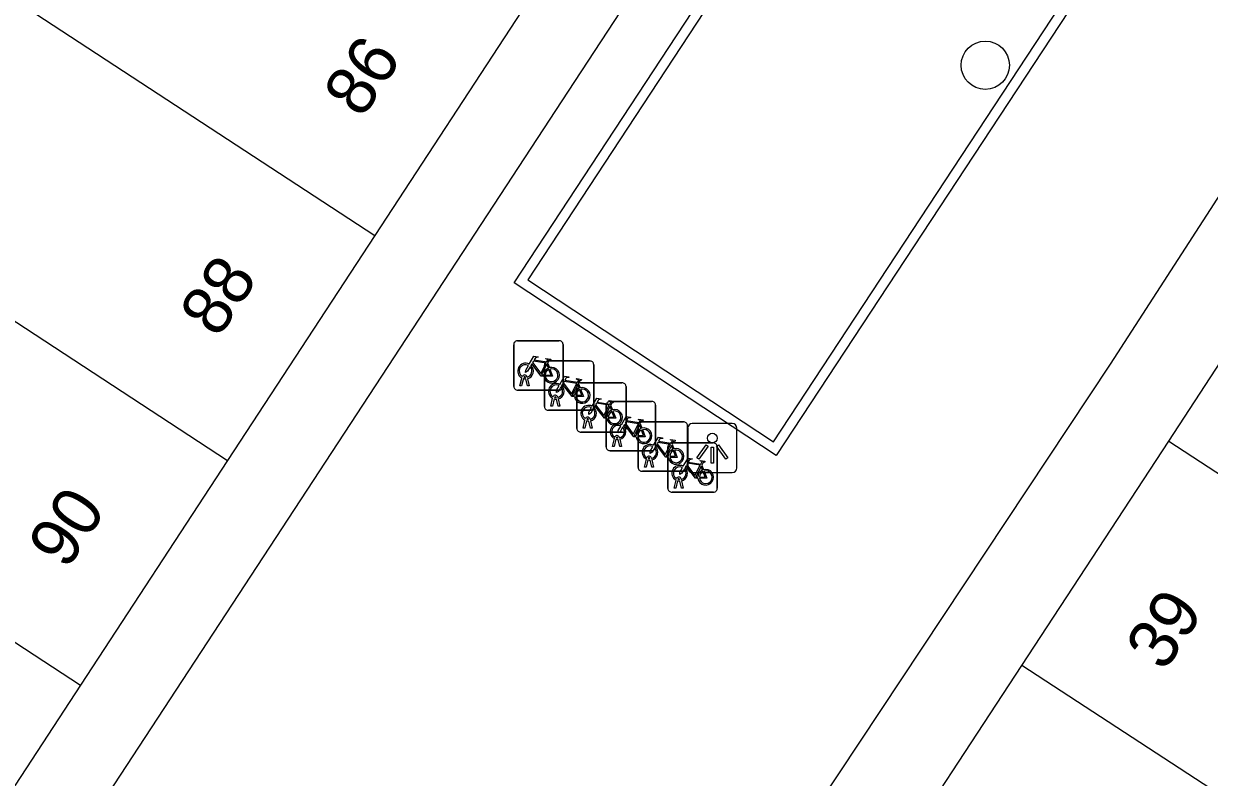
# Model space of a CAD drawing. Extents: x 155640 to 156810, y 382822 to 384046.
# Drawn here: x 156449.06 to 156473.07, y 383747.07 to 383762.35 of the extents above; entities that cross this region are included whole.
import ezdxf

# ---------------------------------------------------------------- set-up
doc = ezdxf.new("R2010")
doc.units = 0
for name, color, linetype in [('IMGEO_Boom', 7, 'Continuous'), ('IMGEO_Fietsenrek', 7, 'Continuous'), ('IMGEO_Lichtpunt', 7, 'Continuous'), ('IMGEO_Lijnafwatering', 7, 'Continuous'), ('IMGEO_Muur', 7, 'Continuous'), ('IMGEO_Pand', 7, 'Continuous'), ('IMGEO_Pand_nummerreeks', 7, 'Continuous')]:
    doc.layers.add(name, color=color, linetype=linetype)

msp = doc.modelspace()

# ---------------------------------------------------------------- linework, layer by layer
at = {"layer": 'IMGEO_Boom'}
msp.add_circle((156468.536, 383761.508), 0.489, dxfattribs=at)
at = {"layer": 'IMGEO_Fietsenrek'}
for p, q in [((156458.983, 383754.998), (156458.983, 383755.839)), ((156458.983, 383755.839), (156458.983, 383754.998)), ((156459.058, 383755.923), (156459.899, 383755.923)), ((156459.899, 383755.923), (156459.058, 383755.923)), ((156459.983, 383755.848), (156459.983, 383755.007)), ((156459.983, 383755.007), (156459.983, 383755.848)), ((156459.67, 383755.472), (156459.706, 383755.377)), ((156459.68, 383755.512), (156460.521, 383755.512)), ((156460.521, 383755.512), (156459.68, 383755.512)), ((156459.605, 383754.587), (156459.605, 383755.428)), ((156459.605, 383755.428), (156459.605, 383754.587)), ((156460.605, 383755.437), (156460.605, 383754.596)), ((156460.605, 383754.596), (156460.605, 383755.437)), ((156459.11, 383755.007), (156459.149, 383755.167)), ((156459.144, 383755.007), (156459.11, 383755.007)), ((156459.179, 383755.155), (156459.144, 383755.007)), ((156459.221, 383755.179), (156459.22, 383755.183)), ((156459.262, 383755.007), (156459.228, 383755.149)), ((156459.252, 383755.19), (156459.253, 383755.183)), ((156459.26, 383755.153), (156459.295, 383755.007)), ((156459.295, 383755.007), (156459.262, 383755.007)), ((156460.26, 383754.144), (156460.26, 383754.985)), ((156460.26, 383754.985), (156460.26, 383754.144)), ((156460.292, 383755.061), (156460.328, 383754.966)), ((156460.335, 383755.069), (156461.176, 383755.069)), ((156461.176, 383755.069), (156460.335, 383755.069)), ((156461.26, 383754.994), (156461.26, 383754.153)), ((156461.26, 383754.153), (156461.26, 383754.994)), ((156459.908, 383754.923), (156459.067, 383754.923)), ((156459.067, 383754.923), (156459.908, 383754.923)), ((156459.732, 383754.596), (156459.771, 383754.756)), ((156459.801, 383754.744), (156459.766, 383754.596)), ((156459.843, 383754.768), (156459.842, 383754.772)), ((156459.884, 383754.596), (156459.85, 383754.738)), ((156459.874, 383754.779), (156459.875, 383754.772)), ((156459.882, 383754.742), (156459.917, 383754.596)), ((156460.53, 383754.512), (156459.689, 383754.512)), ((156459.689, 383754.512), (156460.53, 383754.512)), ((156459.766, 383754.596), (156459.732, 383754.596)), ((156459.917, 383754.596), (156459.884, 383754.596)), ((156460.856, 383753.769), (156460.856, 383754.61)), ((156460.856, 383754.61), (156460.856, 383753.769)), ((156460.931, 383754.694), (156461.772, 383754.694)), ((156461.772, 383754.694), (156460.931, 383754.694)), ((156460.947, 383754.618), (156460.983, 383754.523)), ((156461.856, 383754.619), (156461.856, 383753.778)), ((156461.856, 383753.778), (156461.856, 383754.619)), ((156460.387, 383754.153), (156460.426, 383754.313)), ((156460.456, 383754.301), (156460.421, 383754.153)), ((156460.498, 383754.325), (156460.497, 383754.329)), ((156460.539, 383754.153), (156460.505, 383754.295)), ((156460.529, 383754.336), (156460.53, 383754.329)), ((156460.537, 383754.299), (156460.572, 383754.153)), ((156461.58, 383754.277), (156462.421, 383754.277)), ((156462.421, 383754.277), (156461.58, 383754.277)), ((156461.185, 383754.069), (156460.344, 383754.069)), ((156460.344, 383754.069), (156461.185, 383754.069)), ((156460.421, 383754.153), (156460.387, 383754.153)), ((156460.572, 383754.153), (156460.539, 383754.153)), ((156461.505, 383753.352), (156461.505, 383754.193)), ((156461.505, 383754.193), (156461.505, 383753.352)), ((156461.543, 383754.243), (156461.579, 383754.148)), ((156462.505, 383754.202), (156462.505, 383753.361)), ((156462.505, 383753.361), (156462.505, 383754.202)), ((156460.983, 383753.778), (156461.022, 383753.938)), ((156461.017, 383753.778), (156460.983, 383753.778)), ((156461.052, 383753.926), (156461.017, 383753.778)), ((156461.094, 383753.95), (156461.093, 383753.954)), ((156461.135, 383753.778), (156461.101, 383753.92)), ((156461.125, 383753.961), (156461.126, 383753.954)), ((156461.133, 383753.924), (156461.168, 383753.778)), ((156461.168, 383753.778), (156461.135, 383753.778)), ((156462.181, 383753.853), (156463.022, 383753.853)), ((156463.022, 383753.853), (156462.181, 383753.853)), ((156462.192, 383753.826), (156462.228, 383753.731)), ((156463.106, 383753.778), (156463.106, 383752.937)), ((156463.106, 383752.937), (156463.106, 383753.778)), ((156461.781, 383753.694), (156460.94, 383753.694)), ((156460.94, 383753.694), (156461.781, 383753.694)), ((156461.743, 383753.533), (156461.742, 383753.537)), ((156461.774, 383753.544), (156461.775, 383753.537)), ((156462.106, 383752.928), (156462.106, 383753.769)), ((156462.106, 383753.769), (156462.106, 383752.928)), ((156461.632, 383753.361), (156461.671, 383753.521)), ((156461.666, 383753.361), (156461.632, 383753.361)), ((156461.701, 383753.509), (156461.666, 383753.361)), ((156461.784, 383753.361), (156461.75, 383753.503)), ((156461.782, 383753.507), (156461.817, 383753.361)), ((156461.817, 383753.361), (156461.784, 383753.361)), ((156462.793, 383753.402), (156462.829, 383753.307)), ((156462.43, 383753.277), (156461.589, 383753.277)), ((156461.589, 383753.277), (156462.43, 383753.277)), ((156462.233, 383752.937), (156462.272, 383753.097)), ((156462.302, 383753.085), (156462.267, 383752.937)), ((156462.344, 383753.109), (156462.343, 383753.113)), ((156462.385, 383752.937), (156462.351, 383753.079)), ((156462.375, 383753.12), (156462.376, 383753.113)), ((156462.383, 383753.083), (156462.418, 383752.937)), ((156463.031, 383752.853), (156462.19, 383752.853)), ((156462.19, 383752.853), (156463.031, 383752.853)), ((156462.267, 383752.937), (156462.233, 383752.937)), ((156462.418, 383752.937), (156462.385, 383752.937))]:
    msp.add_line(p, q, dxfattribs=at)
for points in [[(156459.296, 383755.449), (156459.391, 383755.613), (156459.477, 383755.599), (156459.479, 383755.59), (156459.423, 383755.579), (156459.396, 383755.534), (156459.652, 383755.493)], [(156459.592, 383755.205), (156459.542, 383755.205), (156459.351, 383755.456), (156459.332, 383755.424)], [(156459.639, 383755.468), (156459.382, 383755.509), (156459.365, 383755.48), (156459.532, 383755.26), (156459.639, 383755.468)], [(156459.652, 383755.493), (156459.677, 383755.542), (156459.671, 383755.546), (156459.648, 383755.55), (156459.636, 383755.557), (156459.635, 383755.56), (156459.637, 383755.565), (156459.732, 383755.55), (156459.734, 383755.54), (156459.724, 383755.527), (156459.712, 383755.521), (156459.698, 383755.527), (156459.67, 383755.472)], [(156459.317, 383755.397), (156459.265, 383755.307), (156459.225, 383755.282), (156459.226, 383755.329), (156459.281, 383755.423)], [(156459.687, 383755.37), (156459.657, 383755.447), (156459.548, 383755.229), (156459.591, 383755.229)], [(156459.621, 383755.229), (156459.741, 383755.228), (156459.697, 383755.342)], [(156459.717, 383755.349), (156459.772, 383755.204), (156459.622, 383755.204)], [(156459.939, 383754.986), (156459.887, 383754.896), (156459.847, 383754.871), (156459.848, 383754.918), (156459.903, 383755.012)], [(156459.918, 383755.038), (156460.013, 383755.202), (156460.099, 383755.188), (156460.101, 383755.179), (156460.045, 383755.168), (156460.018, 383755.123), (156460.274, 383755.082)], [(156460.214, 383754.794), (156460.164, 383754.794), (156459.973, 383755.045), (156459.954, 383755.013)], [(156460.261, 383755.057), (156460.004, 383755.098), (156459.987, 383755.069), (156460.154, 383754.849), (156460.261, 383755.057)], [(156460.309, 383754.959), (156460.279, 383755.036), (156460.17, 383754.818), (156460.213, 383754.818)], [(156460.274, 383755.082), (156460.299, 383755.131), (156460.293, 383755.135), (156460.27, 383755.139), (156460.258, 383755.146), (156460.257, 383755.149), (156460.259, 383755.154), (156460.354, 383755.139), (156460.356, 383755.129), (156460.346, 383755.116), (156460.334, 383755.11), (156460.32, 383755.116), (156460.292, 383755.061)], [(156460.243, 383754.818), (156460.363, 383754.817), (156460.319, 383754.931)], [(156460.339, 383754.938), (156460.394, 383754.793), (156460.244, 383754.793)], [(156460.573, 383754.595), (156460.668, 383754.759), (156460.754, 383754.745), (156460.756, 383754.736), (156460.7, 383754.725), (156460.673, 383754.68), (156460.929, 383754.639)], [(156460.594, 383754.543), (156460.542, 383754.453), (156460.502, 383754.428), (156460.503, 383754.475), (156460.558, 383754.569)], [(156460.869, 383754.351), (156460.819, 383754.351), (156460.628, 383754.602), (156460.609, 383754.57)], [(156460.916, 383754.614), (156460.659, 383754.655), (156460.642, 383754.626), (156460.809, 383754.406), (156460.916, 383754.614)], [(156460.964, 383754.516), (156460.934, 383754.593), (156460.825, 383754.375), (156460.868, 383754.375)], [(156460.994, 383754.495), (156461.049, 383754.35), (156460.899, 383754.35)], [(156460.929, 383754.639), (156460.954, 383754.688), (156460.948, 383754.692), (156460.925, 383754.696), (156460.913, 383754.703), (156460.912, 383754.706), (156460.914, 383754.711), (156461.009, 383754.696), (156461.011, 383754.686), (156461.001, 383754.673), (156460.989, 383754.667), (156460.975, 383754.673), (156460.947, 383754.618)], [(156460.898, 383754.375), (156461.018, 383754.374), (156460.974, 383754.488)], [(156461.169, 383754.22), (156461.264, 383754.384), (156461.35, 383754.37), (156461.352, 383754.361), (156461.296, 383754.35), (156461.269, 383754.305), (156461.525, 383754.264)], [(156461.512, 383754.239), (156461.255, 383754.28), (156461.238, 383754.251), (156461.405, 383754.031), (156461.512, 383754.239)], [(156461.525, 383754.264), (156461.55, 383754.313), (156461.544, 383754.317), (156461.521, 383754.321), (156461.509, 383754.328), (156461.508, 383754.331), (156461.51, 383754.336), (156461.605, 383754.321), (156461.607, 383754.311), (156461.597, 383754.298), (156461.585, 383754.292), (156461.571, 383754.298), (156461.543, 383754.243)], [(156461.19, 383754.168), (156461.138, 383754.078), (156461.098, 383754.053), (156461.099, 383754.1), (156461.154, 383754.194)], [(156461.465, 383753.976), (156461.415, 383753.976), (156461.224, 383754.227), (156461.205, 383754.195)], [(156461.56, 383754.141), (156461.53, 383754.218), (156461.421, 383754), (156461.464, 383754)], [(156461.494, 383754), (156461.614, 383753.999), (156461.57, 383754.113)], [(156461.59, 383754.12), (156461.645, 383753.975), (156461.495, 383753.975)], [(156461.839, 383753.751), (156461.787, 383753.661), (156461.747, 383753.636), (156461.748, 383753.683), (156461.803, 383753.777)], [(156461.818, 383753.803), (156461.913, 383753.967), (156461.999, 383753.953), (156462.001, 383753.944), (156461.945, 383753.933), (156461.918, 383753.888), (156462.174, 383753.847)], [(156462.114, 383753.559), (156462.064, 383753.559), (156461.873, 383753.81), (156461.854, 383753.778)], [(156462.161, 383753.822), (156461.904, 383753.863), (156461.887, 383753.834), (156462.054, 383753.614), (156462.161, 383753.822)], [(156462.209, 383753.724), (156462.179, 383753.801), (156462.07, 383753.583), (156462.113, 383753.583)], [(156462.174, 383753.847), (156462.199, 383753.896), (156462.193, 383753.9), (156462.17, 383753.904), (156462.158, 383753.911), (156462.157, 383753.914), (156462.159, 383753.919), (156462.254, 383753.904), (156462.256, 383753.894), (156462.246, 383753.881), (156462.234, 383753.875), (156462.22, 383753.881), (156462.192, 383753.826)], [(156462.143, 383753.583), (156462.263, 383753.582), (156462.219, 383753.696)], [(156462.239, 383753.703), (156462.294, 383753.558), (156462.144, 383753.558)], [(156462.419, 383753.379), (156462.514, 383753.543), (156462.6, 383753.529), (156462.602, 383753.52), (156462.546, 383753.509), (156462.519, 383753.464), (156462.775, 383753.423)], [(156462.44, 383753.327), (156462.388, 383753.237), (156462.348, 383753.212), (156462.349, 383753.259), (156462.404, 383753.353)], [(156462.715, 383753.135), (156462.665, 383753.135), (156462.474, 383753.386), (156462.455, 383753.354)], [(156462.762, 383753.398), (156462.505, 383753.439), (156462.488, 383753.41), (156462.655, 383753.19), (156462.762, 383753.398)], [(156462.81, 383753.3), (156462.78, 383753.377), (156462.671, 383753.159), (156462.714, 383753.159)], [(156462.775, 383753.423), (156462.8, 383753.472), (156462.794, 383753.476), (156462.771, 383753.48), (156462.759, 383753.487), (156462.758, 383753.49), (156462.76, 383753.495), (156462.855, 383753.48), (156462.857, 383753.47), (156462.847, 383753.457), (156462.835, 383753.451), (156462.821, 383753.457), (156462.793, 383753.402)], [(156462.744, 383753.159), (156462.864, 383753.158), (156462.82, 383753.272)], [(156462.84, 383753.279), (156462.895, 383753.134), (156462.745, 383753.134)]]:
    msp.add_lwpolyline(points, dxfattribs=at)
for centre, radius, start, end in [((156459.061, 383755.845), 0.0779, 92.4484, 184.2845), ((156459.061, 383755.845), 0.0779, 92.4484, 184.2845), ((156459.905, 383755.845), 0.0779, 2.4484, 94.2845), ((156459.905, 383755.845), 0.0779, 2.4484, 94.2845), ((156459.223, 383755.308), 0.159, 62.6766, 242.1369), ((156459.683, 383755.434), 0.0779, 92.4484, 184.2845), ((156459.683, 383755.434), 0.0779, 92.4484, 184.2845), ((156460.527, 383755.434), 0.0779, 2.4484, 94.2845), ((156460.527, 383755.434), 0.0779, 2.4484, 94.2845), ((156459.223, 383755.308), 0.129, 63.3192, 238.903), ((156459.203, 383755.179), 0.0499, 12.8025, 158.6934), ((156459.223, 383755.308), 0.129, 283.6043, 43.4302), ((156459.223, 383755.308), 0.159, 283.5766, 46.6042), ((156459.75, 383755.224), 0.159, 113.3408, 178.3217), ((156459.75, 383755.224), 0.159, 187.0065, 105.7708), ((156459.75, 383755.224), 0.129, 113.923, 177.9556), ((156459.75, 383755.224), 0.129, 188.6715, 104.5883), ((156459.061, 383755.001), 0.0779, 182.4484, 274.2845), ((156459.061, 383755.001), 0.0779, 182.4484, 274.2845), ((156459.223, 383755.308), 0.159, 253.9967, 271.7867), ((156459.203, 383755.179), 0.0174, 12.8025, 163.4502), ((156459.223, 383755.308), 0.129, 253.415, 269.0204), ((156459.845, 383754.897), 0.159, 62.6766, 242.1369), ((156459.845, 383754.897), 0.129, 63.3192, 238.903), ((156459.845, 383754.897), 0.129, 283.6043, 43.4302), ((156459.845, 383754.897), 0.159, 283.5766, 46.6042), ((156459.905, 383755.001), 0.0779, 272.4484, 4.2845), ((156459.905, 383755.001), 0.0779, 272.4484, 4.2845), ((156460.338, 383754.991), 0.0779, 92.4484, 184.2845), ((156460.338, 383754.991), 0.0779, 92.4484, 184.2845), ((156461.182, 383754.991), 0.0779, 2.4484, 94.2845), ((156461.182, 383754.991), 0.0779, 2.4484, 94.2845), ((156459.825, 383754.768), 0.0499, 12.8025, 158.6934), ((156459.845, 383754.897), 0.159, 253.9967, 271.7867), ((156459.825, 383754.768), 0.0174, 12.8025, 163.4502), ((156459.845, 383754.897), 0.129, 253.415, 269.0204), ((156460.372, 383754.813), 0.159, 113.3408, 178.3217), ((156460.372, 383754.813), 0.159, 187.0065, 105.7708), ((156460.372, 383754.813), 0.129, 113.923, 177.9556), ((156460.372, 383754.813), 0.129, 188.6715, 104.5883), ((156459.683, 383754.59), 0.0779, 182.4484, 274.2845), ((156459.683, 383754.59), 0.0779, 182.4484, 274.2845), ((156460.5, 383754.454), 0.159, 62.6766, 242.1369), ((156460.5, 383754.454), 0.129, 63.3192, 238.903), ((156460.527, 383754.59), 0.0779, 272.4484, 4.2845), ((156460.527, 383754.59), 0.0779, 272.4484, 4.2845), ((156460.5, 383754.454), 0.129, 283.6043, 43.4302), ((156460.5, 383754.454), 0.159, 283.5766, 46.6042), ((156460.934, 383754.616), 0.0779, 92.4484, 184.2845), ((156460.934, 383754.616), 0.0779, 92.4484, 184.2845), ((156461.027, 383754.37), 0.159, 113.3408, 178.3217), ((156461.027, 383754.37), 0.159, 187.0065, 105.7708), ((156461.027, 383754.37), 0.129, 188.6715, 104.5883), ((156461.778, 383754.616), 0.0779, 2.4484, 94.2845), ((156461.778, 383754.616), 0.0779, 2.4484, 94.2845), ((156460.48, 383754.325), 0.0499, 12.8025, 158.6934), ((156460.5, 383754.454), 0.159, 253.9967, 271.7867), ((156460.48, 383754.325), 0.0174, 12.8025, 163.4502), ((156460.5, 383754.454), 0.129, 253.415, 269.0204), ((156461.027, 383754.37), 0.129, 113.923, 177.9556), ((156461.583, 383754.199), 0.0779, 92.4484, 184.2845), ((156461.583, 383754.199), 0.0779, 92.4484, 184.2845), ((156462.427, 383754.199), 0.0779, 2.4484, 94.2845), ((156462.427, 383754.199), 0.0779, 2.4484, 94.2845), ((156460.338, 383754.147), 0.0779, 182.4484, 274.2845), ((156460.338, 383754.147), 0.0779, 182.4484, 274.2845), ((156461.096, 383754.079), 0.159, 62.6766, 242.1369), ((156461.096, 383754.079), 0.129, 63.3192, 238.903), ((156461.096, 383754.079), 0.129, 283.6043, 43.4302), ((156461.096, 383754.079), 0.159, 283.5766, 46.6042), ((156461.182, 383754.147), 0.0779, 272.4484, 4.2845), ((156461.182, 383754.147), 0.0779, 272.4484, 4.2845), ((156461.623, 383753.995), 0.159, 113.3408, 178.3217), ((156461.623, 383753.995), 0.159, 187.0065, 105.7708), ((156461.623, 383753.995), 0.129, 113.923, 177.9556), ((156461.623, 383753.995), 0.129, 188.6715, 104.5883), ((156461.076, 383753.95), 0.0499, 12.8025, 158.6934), ((156461.096, 383754.079), 0.159, 253.9967, 271.7867), ((156461.076, 383753.95), 0.0174, 12.8025, 163.4502), ((156461.096, 383754.079), 0.129, 253.415, 269.0204), ((156461.745, 383753.662), 0.159, 62.6766, 242.1369), ((156461.745, 383753.662), 0.129, 63.3192, 238.903), ((156461.778, 383753.772), 0.0779, 272.4484, 4.2845), ((156461.778, 383753.772), 0.0779, 272.4484, 4.2845), ((156461.745, 383753.662), 0.159, 283.5766, 46.6042), ((156462.184, 383753.775), 0.0779, 92.4484, 184.2845), ((156462.184, 383753.775), 0.0779, 92.4484, 184.2845), ((156463.028, 383753.775), 0.0779, 2.4484, 94.2845), ((156463.028, 383753.775), 0.0779, 2.4484, 94.2845), ((156460.934, 383753.772), 0.0779, 182.4484, 274.2845), ((156460.934, 383753.772), 0.0779, 182.4484, 274.2845), ((156461.725, 383753.533), 0.0499, 12.8025, 158.6934), ((156461.725, 383753.533), 0.0174, 12.8025, 163.4502), ((156461.745, 383753.662), 0.129, 253.415, 269.0204), ((156461.745, 383753.662), 0.129, 283.6043, 43.4302), ((156462.272, 383753.578), 0.159, 113.3408, 178.3217), ((156462.272, 383753.578), 0.159, 187.0065, 105.7708), ((156462.272, 383753.578), 0.129, 113.923, 177.9556), ((156462.272, 383753.578), 0.129, 188.6715, 104.5883), ((156461.583, 383753.355), 0.0779, 182.4484, 274.2845), ((156461.583, 383753.355), 0.0779, 182.4484, 274.2845), ((156461.745, 383753.662), 0.159, 253.9967, 271.7867), ((156462.346, 383753.238), 0.159, 62.6766, 242.1369), ((156462.346, 383753.238), 0.129, 63.3192, 238.903), ((156462.346, 383753.238), 0.129, 283.6043, 43.4302), ((156462.346, 383753.238), 0.159, 283.5766, 46.6042), ((156462.427, 383753.355), 0.0779, 272.4484, 4.2845), ((156462.427, 383753.355), 0.0779, 272.4484, 4.2845), ((156462.873, 383753.154), 0.159, 113.3408, 178.3217), ((156462.873, 383753.154), 0.159, 187.0065, 105.7708), ((156462.326, 383753.109), 0.0499, 12.8025, 158.6934), ((156462.346, 383753.238), 0.159, 253.9967, 271.7867), ((156462.326, 383753.109), 0.0174, 12.8025, 163.4502), ((156462.346, 383753.238), 0.129, 253.415, 269.0204), ((156462.873, 383753.154), 0.129, 113.923, 177.9556), ((156462.873, 383753.154), 0.129, 188.6715, 104.5883), ((156462.184, 383752.931), 0.0779, 182.4484, 274.2845), ((156462.184, 383752.931), 0.0779, 182.4484, 274.2845), ((156463.028, 383752.931), 0.0779, 272.4484, 4.2845), ((156463.028, 383752.931), 0.0779, 272.4484, 4.2845)]:
    msp.add_arc(centre, radius, start, end, dxfattribs=at)
at = {"layer": 'IMGEO_Lichtpunt'}
for p, q in [((156462.507, 383754.15), (156462.507, 383753.343)), ((156462.507, 383754.15), (156462.507, 383753.343)), ((156463.409, 383754.245), (156462.601, 383754.245)), ((156463.409, 383754.245), (156462.601, 383754.245)), ((156463.503, 383753.343), (156463.503, 383754.15)), ((156463.503, 383753.343), (156463.503, 383754.15)), ((156462.601, 383753.249), (156463.409, 383753.249)), ((156462.601, 383753.249), (156463.409, 383753.249))]:
    msp.add_line(p, q, dxfattribs=at)
for points in [[(156462.881, 383753.814), (156462.92, 383753.786), (156462.732, 383753.524), (156462.694, 383753.551), (156462.881, 383753.814)], [(156463.093, 383753.786), (156463.131, 383753.813), (156463.318, 383753.551), (156463.279, 383753.523), (156463.093, 383753.786)], [(156462.983, 383753.766), (156463.03, 383753.766), (156463.03, 383753.444), (156462.983, 383753.444), (156462.983, 383753.766)]]:
    msp.add_lwpolyline(points, dxfattribs=at)
msp.add_circle((156463.006, 383753.948), 0.0994, dxfattribs=at)
for centre, start, end in [((156462.601, 383754.15), 90, 180), ((156462.601, 383754.15), 90, 180), ((156463.409, 383754.15), 0, 90), ((156463.409, 383754.15), 0, 90), ((156462.601, 383753.343), 180, 270), ((156462.601, 383753.343), 180, 270), ((156463.409, 383753.343), 270, 0), ((156463.409, 383753.343), 270, 360)]:
    msp.add_arc(centre, 0.0946, start, end, dxfattribs=at)
at = {"layer": 'IMGEO_Lijnafwatering'}
for points in [[(156472.253, 383779.565), (156460.088, 383760.982)], [(156481.391, 383771.435), (156471.067, 383755.451)], [(156460.088, 383760.982), (156447.726, 383742.098)], [(156471.067, 383755.451), (156459.635, 383738.197)]]:
    msp.add_lwpolyline(points, dxfattribs=at)
at = {"layer": 'IMGEO_Muur'}
for points in [[(156464.303, 383753.596), (156458.99, 383757.098), (156466.993, 383769.287), (156472.306, 383765.783), (156464.303, 383753.596)], [(156464.246, 383753.873), (156472.029, 383765.726), (156467.05, 383769.009), (156459.267, 383757.155), (156464.246, 383753.873)]]:
    msp.add_lwpolyline(points, dxfattribs=at)
at = {"layer": 'IMGEO_Pand'}
for points in [[(156445.081, 383765.315), (156456.167, 383758.053)], [(156459.148, 383762.611), (156456.167, 383758.053)], [(156442.097, 383760.76), (156453.187, 383753.496)], [(156472.251, 383753.89), (156475.417, 383758.73), (156475.806, 383758.471)], [(156456.167, 383758.053), (156453.187, 383753.496)], [(156439.113, 383756.204), (156450.206, 383748.938)], [(156469.274, 383749.341), (156472.251, 383753.89)], [(156472.251, 383753.89), (156479.445, 383749.193)], [(156453.187, 383753.496), (156450.206, 383748.938)], [(156466.337, 383744.851), (156469.274, 383749.341)], [(156476.467, 383744.644), (156469.274, 383749.341)], [(156450.206, 383748.938), (156447.225, 383744.38)]]:
    msp.add_lwpolyline(points, dxfattribs=at)

# ---------------------------------------------------------------- texts
at = {"layer": 'IMGEO_Pand_nummerreeks'}
for s, rotation, p in [('86', 56.6197, (156455.91, 383760.405)), ('88', 56.6197, (156452.997, 383755.951)), ('90', 56.6197, (156449.927, 383751.257)), ('39', 56.7973, (156472.163, 383749.191))]:
    msp.add_text(s, height=1, rotation=rotation, dxfattribs=at).set_placement(p)

doc.saveas('drawing.dxf')
